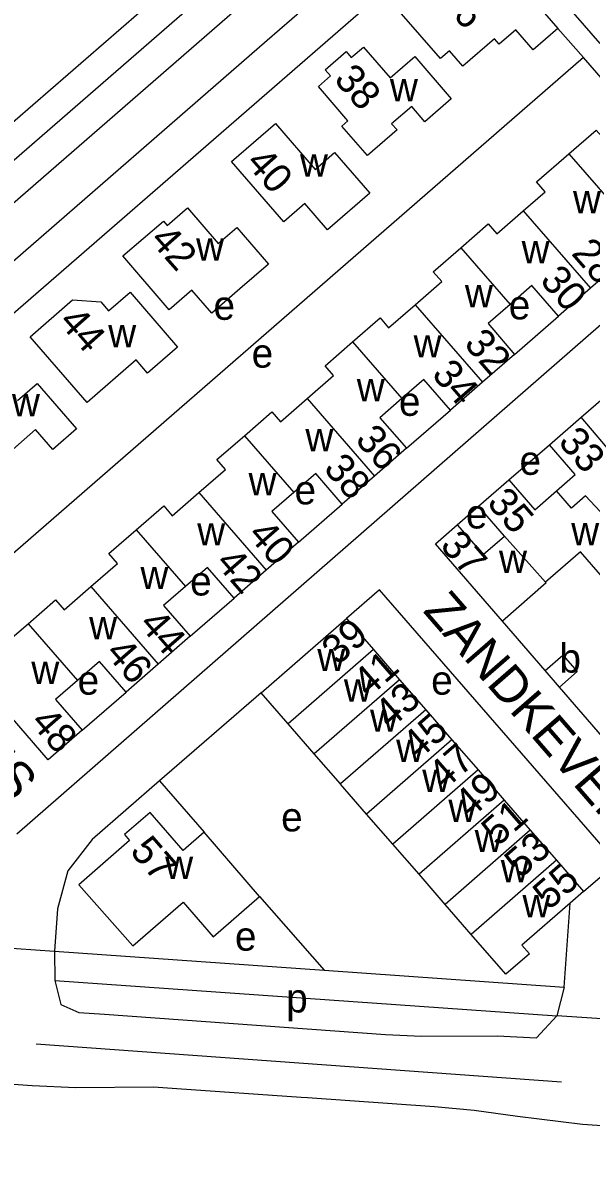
# Model space of a CAD drawing. Extents: x 155854 to 157362, y 383621 to 384685.
# Drawn here: x 155992.5 to 156071.1, y 383977 to 384135.3 of the extents above; entities that cross this region are included whole.
import ezdxf

# ---------------------------------------------------------------- set-up
doc = ezdxf.new("R2010")
doc.units = 0
for name, color, linetype in [('BLT_Basislijn', 7, 'Continuous'), ('BLT_Bebouwing', 7, 'Continuous'), ('BLT_Centroide', 7, 'Continuous'), ('BLT_Huisnummer', 7, 'Continuous'), ('BLT_Huisnummer_ tussenligend', 7, 'Continuous'), ('BLT_Onderverdeling_panden', 7, 'Continuous'), ('BLT_Straatnaam', 7, 'Continuous'), ('BLT_Vlakafsluiter', 7, 'Continuous')]:
    doc.layers.add(name, color=color, linetype=linetype)

msp = doc.modelspace()

# ---------------------------------------------------------------- linework, layer by layer
at = {"layer": 'BLT_Basislijn'}
for p, q in [((156026.31, 384132.88), (156143.26, 384234.47)), ((155892.15, 384035.54), (156042.02, 384165.73)), ((156043.1, 384155.4), (155952.77, 384076.94)), ((156070.03, 384130.46), (156066.5, 384134.49)), ((155909.37, 384031.28), (156026.31, 384132.88)), ((156070.03, 384130.46), (155979.82, 384052.08)), ((156076.93, 384122.52), (156070.03, 384130.46)), ((156111.16, 384127.33), (155991.68, 384023.17)), ((156060.51, 384089.46), (156066.58, 384094.74)), ((156045.56, 384076.48), (156051.63, 384081.75)), ((156059.7, 384072.1), (156065.31, 384076.97)), ((156030.62, 384063.49), (156036.68, 384068.76)), ((156052.56, 384065.89), (156055.53, 384068.47)), ((156015.67, 384050.51), (156021.74, 384055.78)), ((156064.71, 384045.76), (156058.83, 384052.6)), ((156072.64, 384036.63), (156066.69, 384043.48)), ((156000.72, 384037.52), (156006.79, 384042.8)), ((156025.46, 384042.7), (156011.44, 384030.55)), ((156011.44, 384030.55), (156017.61, 384023.43)), ((156025.26, 384014.57), (156034.19, 384004.36)), ((155996.9, 384006.98), (156034.19, 384004.36)), ((155996.94, 384002.97), (156066.34, 383998.09)), ((156067.37, 384002.03), (156066.34, 383998.09)), ((156066.34, 383998.09), (156063.55, 383995.03)), ((155994.37, 383994.19), (156067, 383988.93))]:
    msp.add_line(p, q, dxfattribs=at)
for points in [[(156150.65, 384224.45), (156146.11, 384229.67), (156055.9, 384151.3), (156072.3, 384132.42)], [(155949.82, 384080.34), (156040.15, 384158.81)], [(156053.63, 384149.33), (155963.42, 384070.96), (155979.82, 384052.08)], [(156070.04, 384015.24), (156074.62, 384019.2), (156041.83, 384056.94), (156037.26, 384052.98)], [(156011.44, 384030.55), (156006.77, 384026.48), (156002.09, 384022.42), (155998.74, 384018.1), (155997.31, 384012.83), (155996.9, 384006.98)], [(156067.37, 384002.03), (156068.18, 384013.63)], [(155996.9, 384006.98), (155996.94, 384002.97)], [(156034.19, 384004.36), (156067.37, 384002.03)], [(155996.94, 384002.97), (155997.77, 383999.65), (156000.25, 383998.54)], [(156000.25, 383998.54), (156003.83, 383998.28), (156042.66, 383995.5), (156047.65, 383995.27), (156058.11, 383995.31), (156063.55, 383995.03)], [(155999.85, 383988.14), (155993.83, 383988.4), (155985.97, 383988.95), (155966.02, 383991.36), (155924.95, 383994.24)], [(156030.99, 383986.77), (156013.83, 383988), (156010.59, 383988.21), (155999.85, 383988.14)], [(156031.89, 383986.73), (156030.99, 383986.77)], [(156049.41, 383985.5), (156031.89, 383986.73)], [(156060.92, 383984.14), (156054.93, 383984.99), (156049.41, 383985.5)], [(156167.61, 383976.23), (156155.21, 383977.85), (156146.07, 383978.71), (156096.76, 383982.18), (156081.71, 383982.35), (156076.66, 383982.58), (156069.91, 383983.06), (156060.92, 383984.14)]]:
    msp.add_lwpolyline(points, dxfattribs=at)
at = {"layer": 'BLT_Bebouwing'}
for p, q in [((156050.28, 384130.32), (156044.89, 384136.49)), ((156060.67, 384134.31), (156058.38, 384132.32)), ((156063.09, 384131.53), (156060.67, 384134.31)), ((156066.5, 384134.49), (156063.09, 384131.53)), ((156039.61, 384131.91), (156043.31, 384127.66)), ((156057.72, 384133.07), (156053.35, 384129.27)), ((156058.38, 384132.32), (156057.72, 384133.07)), ((156043.31, 384127.66), (156046.7, 384130.59)), ((156046.7, 384130.59), (156051.75, 384124.74)), ((156051.5, 384131.38), (156050.28, 384130.32)), ((156053.35, 384129.27), (156051.5, 384131.38)), ((156037.47, 384121.73), (156033.38, 384126.47)), ((156051.75, 384124.74), (156048.11, 384121.6)), ((156046.28, 384123.72), (156043.51, 384121.33)), ((156048.11, 384121.6), (156046.28, 384123.72)), ((156021.36, 384116.09), (156027.43, 384121.36)), ((156027.43, 384121.36), (156032.93, 384115.02)), ((156036.64, 384120.98), (156037.47, 384121.73)), ((156040.15, 384116.92), (156036.64, 384120.98)), ((156043.51, 384121.33), (156044.25, 384120.46)), ((156044.25, 384120.46), (156040.15, 384116.92)), ((156028.6, 384107.75), (156021.36, 384116.09)), ((156032.93, 384115.02), (156035.61, 384117.35)), ((156035.61, 384117.35), (156040.49, 384111.75)), ((156040.49, 384111.75), (156034.66, 384106.68)), ((156012.48, 384107.26), (156015.28, 384109.68)), ((156015.28, 384109.68), (156019.54, 384104.77)), ((156031.52, 384110.29), (156028.6, 384107.75)), ((156034.66, 384106.68), (156031.52, 384110.29)), ((156006.36, 384103.05), (156011.95, 384107.88)), ((156011.95, 384107.88), (156012.48, 384107.26)), ((156019.54, 384104.77), (156022.09, 384106.98)), ((156022.09, 384106.98), (156026.47, 384101.93)), ((156012.77, 384095.63), (156006.36, 384103.05)), ((156026.47, 384101.93), (156022.52, 384098.51)), ((156075.46, 384102.45), (156071.02, 384098.59)), ((156071.02, 384098.59), (156066.58, 384094.74)), ((156004.36, 384095.46), (156007.36, 384098.07)), ((156007.36, 384098.07), (156013.9, 384090.47)), ((156022.52, 384098.51), (156018.63, 384095.14)), ((155993.53, 384091.9), (155999.39, 384096.98)), ((155999.39, 384096.98), (156003.29, 384096.71)), ((156003.29, 384096.71), (156004.36, 384095.46)), ((156001.4, 384082.82), (155993.53, 384091.9)), ((156013.9, 384090.47), (156009.74, 384086.88)), ((156060.51, 384089.46), (156056.07, 384085.61)), ((156008.18, 384088.68), (156001.4, 384082.82)), ((156009.74, 384086.88), (156008.18, 384088.68)), ((155991.81, 384083.08), (155994.51, 384085.43)), ((155994.51, 384085.43), (155999.96, 384079.18)), ((156056.07, 384085.61), (156051.63, 384081.75)), ((156069.72, 384080.79), (156073.76, 384084.28)), ((156065.31, 384076.97), (156069.72, 384080.79)), ((155994.26, 384079.09), (155989.1, 384074.57)), ((155996.69, 384076.32), (155994.26, 384079.09)), ((155999.96, 384079.18), (155996.69, 384076.32)), ((156045.56, 384076.48), (156041.12, 384072.62)), ((156041.12, 384072.62), (156036.68, 384068.76)), ((156055.53, 384068.47), (156059.7, 384072.1)), ((156059.1, 384064.36), (156055.53, 384068.47)), ((156049.56, 384063.26), (156052.56, 384065.89)), ((156030.62, 384063.49), (156026.18, 384059.64)), ((156058.83, 384052.6), (156049.56, 384063.26)), ((156026.18, 384059.64), (156021.74, 384055.78)), ((156025.46, 384042.7), (156037.26, 384052.98)), ((156037.26, 384052.98), (156041, 384048.67)), ((156015.67, 384050.51), (156011.23, 384046.65)), ((156041, 384048.67), (156044.61, 384044.51)), ((156011.23, 384046.65), (156006.79, 384042.8)), ((156066.69, 384043.48), (156064.71, 384045.76)), ((156044.61, 384044.51), (156048.22, 384040.36)), ((156029.2, 384038.41), (156025.46, 384042.7)), ((156048.22, 384040.36), (156051.83, 384036.2)), ((156032.81, 384034.25), (156029.2, 384038.4)), ((156051.83, 384036.2), (156055.45, 384032.04)), ((156036.43, 384030.1), (156032.81, 384034.25)), ((156055.45, 384032.04), (156059.06, 384027.87)), ((156040.05, 384025.94), (156036.43, 384030.09)), ((156059.06, 384027.87), (156062.67, 384023.72)), ((156010.12, 384026.17), (156006.59, 384023.11)), ((156014.71, 384020.91), (156010.12, 384026.17)), ((156043.66, 384021.79), (156040.05, 384025.94)), ((156006.59, 384023.11), (156007.29, 384022.31)), ((156017.61, 384023.43), (156014.71, 384020.91)), ((156025.26, 384014.57), (156017.61, 384023.43)), ((156062.67, 384023.72), (156066.28, 384019.56)), ((156007.29, 384022.31), (156000.25, 384016.15)), ((156047.29, 384017.62), (156043.66, 384021.79)), ((156066.28, 384019.56), (156070.04, 384015.24)), ((156050.9, 384013.47), (156047.29, 384017.62)), ((156000.25, 384016.15), (156007.72, 384007.75)), ((156070.04, 384015.24), (156068.18, 384013.63)), ((156007.72, 384007.75), (156014.71, 384013.78)), ((156014.71, 384013.78), (156018.83, 384009)), ((156018.83, 384009), (156025.26, 384014.57)), ((156054.51, 384009.32), (156050.9, 384013.47)), ((156068.18, 384013.63), (156061.52, 384007.83)), ((156059.31, 384003.81), (156054.51, 384009.32)), ((156061.52, 384007.83), (156062.56, 384006.63)), ((156062.56, 384006.63), (156059.31, 384003.81))]:
    msp.add_line(p, q, dxfattribs=at)
for points in [[(156060.94, 384140.9), (156066.5, 384134.49)], [(156033.38, 384126.47), (156035.04, 384127.92), (156034.3, 384128.76), (156037.2, 384131.29), (156037.93, 384130.45), (156039.61, 384131.91)], [(156068.01, 384117.16), (156071.8, 384120.45), (156072.99, 384119.09), (156076.93, 384122.52)], [(156061.71, 384109.31), (156064.73, 384111.93), (156063.55, 384113.29), (156068.01, 384117.16)], [(156053.06, 384104.17), (156056.86, 384107.47), (156058.04, 384106.11), (156061.71, 384109.31)], [(156046.76, 384096.32), (156050.44, 384099.52), (156049.26, 384100.88), (156053.06, 384104.17)], [(156066.58, 384094.74), (156062.9, 384098.97), (156059.87, 384096.34)], [(156018.63, 384095.14), (156015.88, 384098.32), (156012.77, 384095.63)], [(156038.11, 384091.19), (156041.9, 384094.49), (156043.09, 384093.13), (156046.76, 384096.32)], [(156059.87, 384096.34), (156056.83, 384093.7), (156060.51, 384089.46)], [(156031.81, 384083.34), (156035.49, 384086.54), (156034.31, 384087.89), (156038.11, 384091.19)], [(156051.63, 384081.75), (156047.95, 384085.99), (156044.92, 384083.35)], [(156023.16, 384078.21), (156026.95, 384081.51), (156028.14, 384080.15), (156031.81, 384083.34)], [(156044.92, 384083.35), (156041.88, 384080.71), (156045.56, 384076.48)], [(156016.86, 384070.36), (156020.54, 384073.55), (156019.36, 384074.91), (156023.16, 384078.21)], [(156066.3, 384070.61), (156068.88, 384072.85), (156065.31, 384076.97)], [(156036.68, 384068.76), (156033.01, 384073), (156029.97, 384070.36)], [(156059.7, 384072.1), (156063.28, 384067.98), (156066.3, 384070.61)], [(156008.21, 384065.23), (156012, 384068.53), (156013.18, 384067.17), (156016.86, 384070.36)], [(156029.97, 384070.36), (156026.94, 384067.73), (156030.62, 384063.49)], [(156052.56, 384065.89), (156056.15, 384061.79), (156059.1, 384064.36)], [(156001.91, 384057.38), (156005.59, 384060.57), (156004.41, 384061.93), (156008.21, 384065.23)], [(156076.63, 384054.1), (156069.61, 384062.18), (156064.78, 384057.98)], [(156021.74, 384055.78), (156018.06, 384060.02), (156015.02, 384057.38)], [(156064.78, 384057.98), (156064.87, 384057.88), (156058.83, 384052.6)], [(155993.26, 384052.25), (155997.05, 384055.54), (155998.23, 384054.18), (156001.91, 384057.38)], [(156015.02, 384057.38), (156011.99, 384054.74), (156015.67, 384050.51)], [(155986.7, 384044.17), (155990.64, 384047.59), (155989.46, 384048.95), (155993.26, 384052.25)], [(156006.79, 384042.8), (156003.11, 384047.03), (156000.07, 384044.4)], [(156064.71, 384045.76), (156067.18, 384047.91), (156069.16, 384045.63), (156066.69, 384043.48)], [(156000.72, 384037.52), (155996.02, 384033.44), (155986.7, 384044.17)], [(156000.07, 384044.4), (155997.04, 384041.76), (156000.72, 384037.52)]]:
    msp.add_lwpolyline(points, dxfattribs=at)
at = {"layer": 'BLT_Onderverdeling_panden'}
for p, q in [((156068.01, 384117.16), (156074.81, 384109.32)), ((156061.71, 384109.31), (156071.02, 384098.59)), ((156053.06, 384104.17), (156059.87, 384096.34)), ((156046.76, 384096.32), (156056.07, 384085.61)), ((156038.11, 384091.19), (156044.92, 384083.35)), ((156031.81, 384083.34), (156041.12, 384072.62)), ((156077.82, 384071.2), (156069.72, 384080.79)), ((156023.16, 384078.21), (156029.97, 384070.36)), ((156016.86, 384070.36), (156026.18, 384059.64)), ((156008.21, 384065.23), (156015.02, 384057.38)), ((156059.1, 384064.36), (156064.78, 384057.98)), ((156001.91, 384057.38), (156011.23, 384046.65)), ((155993.26, 384052.25), (156000.07, 384044.4)), ((156041, 384048.67), (156029.2, 384038.41)), ((156044.61, 384044.51), (156032.81, 384034.25)), ((156048.22, 384040.36), (156036.43, 384030.1)), ((156051.83, 384036.2), (156040.05, 384025.94)), ((156055.45, 384032.04), (156043.66, 384021.79)), ((156059.06, 384027.87), (156047.29, 384017.62)), ((156062.67, 384023.72), (156050.9, 384013.47)), ((156066.28, 384019.56), (156054.51, 384009.32))]:
    msp.add_line(p, q, dxfattribs=at)
msp.add_lwpolyline([(156073.02, 384067.03), (156070.3, 384069.89), (156068.38, 384068.21), (156066.3, 384070.61)], dxfattribs=at)
at = {"layer": 'BLT_Vlakafsluiter'}
for p, q in [((155986.95, 384007.69), (155996.9, 384006.98)), ((156080.14, 383997.12), (156066.34, 383998.09))]:
    msp.add_line(p, q, dxfattribs=at)

# ---------------------------------------------------------------- texts
at = {"layer": 'BLT_Centroide'}
for s, p in [('w', (156043.27, 384124.41)), ('w', (156030.84, 384114.03)), ('w', (156068.58, 384108.95)), ('w', (156016.48, 384102.41)), ('w', (156061.48, 384102.03)), ('w', (156053.64, 384095.95)), ('e', (156018.88, 384094.23)), ('e', (156059.7, 384094.29)), ('w', (156004.33, 384090.44)), ('e', (156024.16, 384087.62)), ('w', (156046.54, 384089.03)), ('w', (156038.69, 384082.98)), ('w', (155991.02, 384080.91)), ('e', (156044.52, 384080.96)), ('w', (156031.59, 384076.06)), ('e', (156061.18, 384072.81)), ('w', (156023.73, 384069.98)), ('e', (156030.08, 384068.73)), ('e', (156053.78, 384065.4)), ('w', (156016.63, 384063.06)), ('w', (156068.33, 384063.09)), ('w', (156058.35, 384059.25)), ('w', (156008.78, 384057.02)), ('e', (156015.65, 384056.14)), ('w', (156001.69, 384050.09)), ('b', (156066.7, 384045.49)), ('w', (156033.23, 384045.69)), ('w', (155993.7, 384043.91)), ('e', (156000.1, 384042.44)), ('e', (156048.97, 384042.44)), ('w', (156036.91, 384041.47)), ('w', (156040.52, 384037.31)), ('w', (156044.13, 384033.16)), ('w', (156047.74, 384029)), ('w', (156051.36, 384024.84)), ('e', (156028.23, 384023.55)), ('w', (156054.98, 384020.69)), ('w', (156012.2, 384016.97)), ('w', (156058.59, 384016.53)), ('w', (156061.59, 384011.69)), ('e', (156021.85, 384007.07)), ('p', (156028.93, 383998.53))]:
    msp.add_text(s, height=4, dxfattribs=at).set_placement(p)
at = {"layer": 'BLT_Huisnummer'}
for s, rotation, p in [('36', 311.4651, (156049.84, 384138.57)), ('38', 311.4651, (156035.4, 384127.35)), ('40', 311.4651, (156023.22, 384115.83)), ('42', 311.4651, (156009.96, 384105.16)), ('44', 311.4651, (155997.35, 384093.86)), ('32', 310.9768, (156053.38, 384090.83)), ('34', 310.9768, (156048.91, 384086.6)), ('33', 310.9773, (156066.4, 384077.27)), ('35', 310.9773, (156056.55, 384068.87)), ('40', 310.9768, (156023.48, 384064.45)), ('37', 310.9773, (156050.07, 384062.96)), ('42', 310.9768, (156019.03, 384060.58)), ('39', 40.9773, (156036.04, 384046.38)), ('48', 310.9768, (155993.44, 384038.54)), ('45', 40.9773, (156047.11, 384033.24)), ('49', 40.9773, (156054.33, 384025.14)), ('57', 310.9773, (156007.2, 384020.74)), ('55', 40.9773, (156065.23, 384012.55))]:
    msp.add_text(s, height=4, rotation=rotation, dxfattribs=at).set_placement(p)
at = {"layer": 'BLT_Huisnummer_ tussenligend'}
for s, rotation, p in [('28', 310.9768, (156068.23, 384103.35)), ('30', 310.9768, (156063.88, 384099.59)), ('36', 310.9768, (156038.33, 384077.58)), ('38', 310.9768, (156033.97, 384073.59)), ('44', 310.9768, (156008.45, 384052.09)), ('46', 310.9768, (156003.81, 384048.12)), ('41', 40.9773, (156040.32, 384041.93)), ('43', 40.9773, (156043.29, 384037.58)), ('47', 40.9773, (156050.72, 384029.11)), ('51', 40.9773, (156058.12, 384021.34)), ('53', 40.9773, (156061.31, 384016.94))]:
    msp.add_text(s, height=4, rotation=rotation, dxfattribs=at).set_placement(p)
at = {"layer": 'BLT_Straatnaam'}
for s, rotation, p in [('ZANDHAGEDIS', 310.9815, (155959.41, 384063.91)), ('ZANDKEVER', 310.9821, (156047.73, 384053.96))]:
    msp.add_text(s, height=5, rotation=rotation, dxfattribs=at).set_placement(p)

doc.saveas('drawing.dxf')
